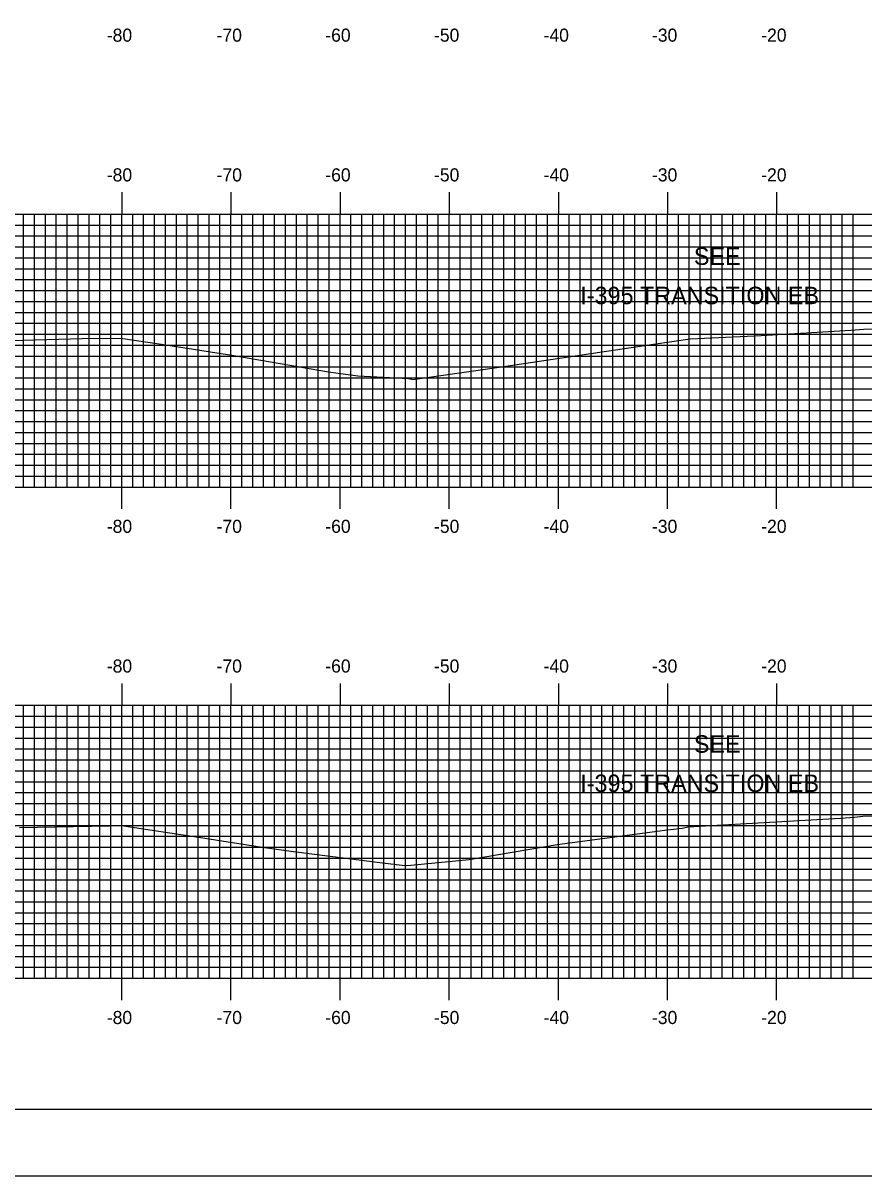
# Model space of a CAD drawing. Extents: x 841782 to 842125, y 363538 to 363758.
# Drawn here: x 841858.3 to 841935.4, y 363537.6 to 363643.2 of the extents above; entities that cross this region are included whole.
import ezdxf

# ---------------------------------------------------------------- set-up
doc = ezdxf.new("R2010")
doc.units = 0
for name, color, linetype in [('ANNOTATION', 7, 'Continuous'), ('BORDER', 7, 'Continuous'), ('H_V ANNOTATION', 7, 'Continuous'), ('M_Roadway_Centerline', 7, 'Continuous'), ('MAJOR', 7, 'Continuous'), ('MINOR', 7, 'Continuous'), ('PLOT BOUNDARY', 7, 'Continuous'), ('S_Roadway_Centerline', 7, 'Continuous')]:
    doc.layers.add(name, color=color, linetype=linetype)

msp = doc.modelspace()

# ---------------------------------------------------------------- linework, layer by layer
at = {"layer": 'BORDER'}
msp.add_lwpolyline([(841797.77, 363543.72), (842117.77, 363543.72), (842117.77, 363753.72), (841797.77, 363753.72)], close=True, dxfattribs=at)
at = {"layer": 'MAJOR'}
for p, q in [((841867.37, 363627.73), (841867.37, 363625.72)), ((841877.37, 363627.73), (841877.37, 363625.72)), ((841887.37, 363627.73), (841887.37, 363625.72)), ((841897.37, 363627.73), (841897.37, 363625.72)), ((841907.37, 363627.73), (841907.37, 363625.72)), ((841917.37, 363627.73), (841917.37, 363625.72)), ((841927.37, 363627.73), (841927.37, 363625.72)), ((841807.37, 363625.72), (842087.37, 363625.72)), ((841807.37, 363625.72), (842087.37, 363625.72)), ((841867.37, 363600.72), (841867.37, 363625.72)), ((841877.37, 363600.72), (841877.37, 363625.72)), ((841887.37, 363600.72), (841887.37, 363625.72)), ((841897.37, 363600.72), (841897.37, 363625.72)), ((841907.37, 363600.72), (841907.37, 363625.72)), ((841917.37, 363600.72), (841917.37, 363625.72)), ((841927.37, 363600.72), (841927.37, 363625.72)), ((841807.37, 363620.72), (842087.37, 363620.72)), ((841807.37, 363615.72), (842087.37, 363615.72)), ((841807.37, 363610.72), (842087.37, 363610.72)), ((841807.37, 363605.72), (842087.37, 363605.72)), ((841807.37, 363600.72), (842087.37, 363600.72)), ((841807.37, 363600.72), (842087.37, 363600.72)), ((841867.37, 363598.72), (841867.37, 363600.72)), ((841877.37, 363598.72), (841877.37, 363600.72)), ((841887.37, 363598.72), (841887.37, 363600.72)), ((841897.37, 363598.72), (841897.37, 363600.72)), ((841907.37, 363598.72), (841907.37, 363600.72)), ((841917.37, 363598.72), (841917.37, 363600.72)), ((841927.37, 363598.72), (841927.37, 363600.72)), ((841867.37, 363582.73), (841867.37, 363580.72)), ((841877.37, 363582.73), (841877.37, 363580.72)), ((841887.37, 363582.73), (841887.37, 363580.72)), ((841897.37, 363582.73), (841897.37, 363580.72)), ((841907.37, 363582.73), (841907.37, 363580.72)), ((841917.37, 363582.73), (841917.37, 363580.72)), ((841927.37, 363582.73), (841927.37, 363580.72)), ((841807.37, 363580.72), (842087.37, 363580.72)), ((841807.37, 363580.72), (842087.37, 363580.72)), ((841867.37, 363555.72), (841867.37, 363580.72)), ((841877.37, 363555.72), (841877.37, 363580.72)), ((841887.37, 363555.72), (841887.37, 363580.72)), ((841897.37, 363555.72), (841897.37, 363580.72)), ((841907.37, 363555.72), (841907.37, 363580.72)), ((841917.37, 363555.72), (841917.37, 363580.72)), ((841927.37, 363555.72), (841927.37, 363580.72)), ((841807.37, 363575.72), (842087.37, 363575.72)), ((841807.37, 363570.72), (842087.37, 363570.72)), ((841807.37, 363565.72), (842087.37, 363565.72)), ((841807.37, 363560.72), (842087.37, 363560.72)), ((841807.37, 363555.72), (842087.37, 363555.72)), ((841807.37, 363555.72), (842087.37, 363555.72)), ((841867.37, 363553.72), (841867.37, 363555.72)), ((841877.37, 363553.72), (841877.37, 363555.72)), ((841887.37, 363553.72), (841887.37, 363555.72)), ((841897.37, 363553.72), (841897.37, 363555.72)), ((841907.37, 363553.72), (841907.37, 363555.72)), ((841917.37, 363553.72), (841917.37, 363555.72)), ((841927.37, 363553.72), (841927.37, 363555.72))]:
    msp.add_line(p, q, dxfattribs=at)
at = {"layer": 'MINOR'}
for p, q in [((841858.37, 363600.72), (841858.37, 363625.72)), ((841859.37, 363600.72), (841859.37, 363625.72)), ((841860.37, 363600.72), (841860.37, 363625.72)), ((841861.37, 363600.72), (841861.37, 363625.72)), ((841862.37, 363600.72), (841862.37, 363625.72)), ((841863.37, 363600.72), (841863.37, 363625.72)), ((841864.37, 363600.72), (841864.37, 363625.72)), ((841865.37, 363600.72), (841865.37, 363625.72)), ((841866.37, 363600.72), (841866.37, 363625.72)), ((841868.37, 363600.72), (841868.37, 363625.72)), ((841869.37, 363600.72), (841869.37, 363625.72)), ((841870.37, 363600.72), (841870.37, 363625.72)), ((841871.37, 363600.72), (841871.37, 363625.72)), ((841872.37, 363600.72), (841872.37, 363625.72)), ((841873.37, 363600.72), (841873.37, 363625.72)), ((841874.37, 363600.72), (841874.37, 363625.72)), ((841875.37, 363600.72), (841875.37, 363625.72)), ((841876.37, 363600.72), (841876.37, 363625.72)), ((841878.37, 363600.72), (841878.37, 363625.72)), ((841879.37, 363600.72), (841879.37, 363625.72)), ((841880.37, 363600.72), (841880.37, 363625.72)), ((841881.37, 363600.72), (841881.37, 363625.72)), ((841882.37, 363600.72), (841882.37, 363625.72)), ((841883.37, 363600.72), (841883.37, 363625.72)), ((841884.37, 363600.72), (841884.37, 363625.72)), ((841885.37, 363600.72), (841885.37, 363625.72)), ((841886.37, 363600.72), (841886.37, 363625.72)), ((841888.37, 363600.72), (841888.37, 363625.72)), ((841889.37, 363600.72), (841889.37, 363625.72)), ((841890.37, 363600.72), (841890.37, 363625.72)), ((841891.37, 363600.72), (841891.37, 363625.72)), ((841892.37, 363600.72), (841892.37, 363625.72)), ((841893.37, 363600.72), (841893.37, 363625.72)), ((841894.37, 363600.72), (841894.37, 363625.72)), ((841895.37, 363600.72), (841895.37, 363625.72)), ((841896.37, 363600.72), (841896.37, 363625.72)), ((841898.37, 363600.72), (841898.37, 363625.72)), ((841899.37, 363600.72), (841899.37, 363625.72)), ((841900.37, 363600.72), (841900.37, 363625.72)), ((841901.37, 363600.72), (841901.37, 363625.72)), ((841902.37, 363600.72), (841902.37, 363625.72)), ((841903.37, 363600.72), (841903.37, 363625.72)), ((841904.37, 363600.72), (841904.37, 363625.72)), ((841905.37, 363600.72), (841905.37, 363625.72)), ((841906.37, 363600.72), (841906.37, 363625.72)), ((841908.37, 363600.72), (841908.37, 363625.72)), ((841909.37, 363600.72), (841909.37, 363625.72)), ((841910.37, 363600.72), (841910.37, 363625.72)), ((841911.37, 363600.72), (841911.37, 363625.72)), ((841912.37, 363600.72), (841912.37, 363625.72)), ((841913.37, 363600.72), (841913.37, 363625.72)), ((841914.37, 363600.72), (841914.37, 363625.72)), ((841915.37, 363600.72), (841915.37, 363625.72)), ((841916.37, 363600.72), (841916.37, 363625.72)), ((841918.37, 363600.72), (841918.37, 363625.72)), ((841919.37, 363600.72), (841919.37, 363625.72)), ((841920.37, 363600.72), (841920.37, 363625.72)), ((841921.37, 363600.72), (841921.37, 363625.72)), ((841922.37, 363600.72), (841922.37, 363625.72)), ((841923.37, 363600.72), (841923.37, 363625.72)), ((841924.37, 363600.72), (841924.37, 363625.72)), ((841925.37, 363600.72), (841925.37, 363625.72)), ((841926.37, 363600.72), (841926.37, 363625.72)), ((841928.37, 363600.72), (841928.37, 363625.72)), ((841929.37, 363600.72), (841929.37, 363625.72)), ((841930.37, 363600.72), (841930.37, 363625.72)), ((841931.37, 363600.72), (841931.37, 363625.72)), ((841932.37, 363600.72), (841932.37, 363625.72)), ((841933.37, 363600.72), (841933.37, 363625.72)), ((841934.37, 363600.72), (841934.37, 363625.72)), ((841807.37, 363624.72), (842087.37, 363624.72)), ((841807.37, 363623.72), (842087.37, 363623.72)), ((841807.37, 363622.72), (842087.37, 363622.72)), ((841807.37, 363621.72), (842087.37, 363621.72)), ((841807.37, 363619.72), (842087.37, 363619.72)), ((841807.37, 363618.72), (842087.37, 363618.72)), ((841807.37, 363617.72), (842087.37, 363617.72)), ((841807.37, 363616.72), (842087.37, 363616.72)), ((841807.37, 363614.72), (842087.37, 363614.72)), ((841807.37, 363613.72), (842087.37, 363613.72)), ((841807.37, 363612.72), (842087.37, 363612.72)), ((841807.37, 363611.72), (842087.37, 363611.72)), ((841807.37, 363609.72), (842087.37, 363609.72)), ((841807.37, 363608.72), (842087.37, 363608.72)), ((841807.37, 363607.72), (842087.37, 363607.72)), ((841807.37, 363606.72), (842087.37, 363606.72)), ((841807.37, 363604.72), (842087.37, 363604.72)), ((841807.37, 363603.72), (842087.37, 363603.72)), ((841807.37, 363602.72), (842087.37, 363602.72)), ((841807.37, 363601.72), (842087.37, 363601.72)), ((841858.37, 363555.72), (841858.37, 363580.72)), ((841859.37, 363555.72), (841859.37, 363580.72)), ((841860.37, 363555.72), (841860.37, 363580.72)), ((841861.37, 363555.72), (841861.37, 363580.72)), ((841862.37, 363555.72), (841862.37, 363580.72)), ((841863.37, 363555.72), (841863.37, 363580.72)), ((841864.37, 363555.72), (841864.37, 363580.72)), ((841865.37, 363555.72), (841865.37, 363580.72)), ((841866.37, 363555.72), (841866.37, 363580.72)), ((841868.37, 363555.72), (841868.37, 363580.72)), ((841869.37, 363555.72), (841869.37, 363580.72)), ((841870.37, 363555.72), (841870.37, 363580.72)), ((841871.37, 363555.72), (841871.37, 363580.72)), ((841872.37, 363555.72), (841872.37, 363580.72)), ((841873.37, 363555.72), (841873.37, 363580.72)), ((841874.37, 363555.72), (841874.37, 363580.72)), ((841875.37, 363555.72), (841875.37, 363580.72)), ((841876.37, 363555.72), (841876.37, 363580.72)), ((841878.37, 363555.72), (841878.37, 363580.72)), ((841879.37, 363555.72), (841879.37, 363580.72)), ((841880.37, 363555.72), (841880.37, 363580.72)), ((841881.37, 363555.72), (841881.37, 363580.72)), ((841882.37, 363555.72), (841882.37, 363580.72)), ((841883.37, 363555.72), (841883.37, 363580.72)), ((841884.37, 363555.72), (841884.37, 363580.72)), ((841885.37, 363555.72), (841885.37, 363580.72)), ((841886.37, 363555.72), (841886.37, 363580.72)), ((841888.37, 363555.72), (841888.37, 363580.72)), ((841889.37, 363555.72), (841889.37, 363580.72)), ((841890.37, 363555.72), (841890.37, 363580.72)), ((841891.37, 363555.72), (841891.37, 363580.72)), ((841892.37, 363555.72), (841892.37, 363580.72)), ((841893.37, 363555.72), (841893.37, 363580.72)), ((841894.37, 363555.72), (841894.37, 363580.72)), ((841895.37, 363555.72), (841895.37, 363580.72)), ((841896.37, 363555.72), (841896.37, 363580.72)), ((841898.37, 363555.72), (841898.37, 363580.72)), ((841899.37, 363555.72), (841899.37, 363580.72)), ((841900.37, 363555.72), (841900.37, 363580.72)), ((841901.37, 363555.72), (841901.37, 363580.72)), ((841902.37, 363555.72), (841902.37, 363580.72)), ((841903.37, 363555.72), (841903.37, 363580.72)), ((841904.37, 363555.72), (841904.37, 363580.72)), ((841905.37, 363555.72), (841905.37, 363580.72)), ((841906.37, 363555.72), (841906.37, 363580.72)), ((841908.37, 363555.72), (841908.37, 363580.72)), ((841909.37, 363555.72), (841909.37, 363580.72)), ((841910.37, 363555.72), (841910.37, 363580.72)), ((841911.37, 363555.72), (841911.37, 363580.72)), ((841912.37, 363555.72), (841912.37, 363580.72)), ((841913.37, 363555.72), (841913.37, 363580.72)), ((841914.37, 363555.72), (841914.37, 363580.72)), ((841915.37, 363555.72), (841915.37, 363580.72)), ((841916.37, 363555.72), (841916.37, 363580.72)), ((841918.37, 363555.72), (841918.37, 363580.72)), ((841919.37, 363555.72), (841919.37, 363580.72)), ((841920.37, 363555.72), (841920.37, 363580.72)), ((841921.37, 363555.72), (841921.37, 363580.72)), ((841922.37, 363555.72), (841922.37, 363580.72)), ((841923.37, 363555.72), (841923.37, 363580.72)), ((841924.37, 363555.72), (841924.37, 363580.72)), ((841925.37, 363555.72), (841925.37, 363580.72)), ((841926.37, 363555.72), (841926.37, 363580.72)), ((841928.37, 363555.72), (841928.37, 363580.72)), ((841929.37, 363555.72), (841929.37, 363580.72)), ((841930.37, 363555.72), (841930.37, 363580.72)), ((841931.37, 363555.72), (841931.37, 363580.72)), ((841932.37, 363555.72), (841932.37, 363580.72)), ((841933.37, 363555.72), (841933.37, 363580.72)), ((841934.37, 363555.72), (841934.37, 363580.72)), ((841807.37, 363579.72), (842087.37, 363579.72)), ((841807.37, 363578.72), (842087.37, 363578.72)), ((841807.37, 363577.72), (842087.37, 363577.72)), ((841807.37, 363576.72), (842087.37, 363576.72)), ((841807.37, 363574.72), (842087.37, 363574.72)), ((841807.37, 363573.72), (842087.37, 363573.72)), ((841807.37, 363572.72), (842087.37, 363572.72)), ((841807.37, 363571.72), (842087.37, 363571.72)), ((841807.37, 363569.72), (842087.37, 363569.72)), ((841807.37, 363568.72), (842087.37, 363568.72)), ((841807.37, 363567.72), (842087.37, 363567.72)), ((841807.37, 363566.72), (842087.37, 363566.72)), ((841807.37, 363564.72), (842087.37, 363564.72)), ((841807.37, 363563.72), (842087.37, 363563.72)), ((841807.37, 363562.72), (842087.37, 363562.72)), ((841807.37, 363561.72), (842087.37, 363561.72)), ((841807.37, 363559.72), (842087.37, 363559.72)), ((841807.37, 363558.72), (842087.37, 363558.72)), ((841807.37, 363557.72), (842087.37, 363557.72)), ((841807.37, 363556.72), (842087.37, 363556.72))]:
    msp.add_line(p, q, dxfattribs=at)
at = {"layer": 'PLOT BOUNDARY'}
msp.add_lwpolyline([(841781.59, 363537.6), (842121.59, 363537.6), (842121.59, 363757.6), (841781.59, 363757.6)], close=True, dxfattribs=at)
at = {"layer": 'S_Roadway_Centerline'}
for points in [[(841854.04, 363614.05), (841863.74, 363614.32), (841865.93, 363614.37), (841867.48, 363614.34), (841871.02, 363613.82), (841877.44, 363612.79), (841886.32, 363611.27), (841888.99, 363610.92), (841893.63, 363610.66), (841894.04, 363610.58), (841899.37, 363611.34), (841901.94, 363611.69), (841916.1, 363613.81), (841919.46, 363614.3), (841921.42, 363614.39), (841925.95, 363614.6), (841934.18, 363615.09), (841935.36, 363615.19), (841938.12, 363615.23)], [(841858.01, 363569.53), (841866.24, 363569.69), (841867.32, 363569.73), (841867.52, 363569.68), (841874.39, 363568.64), (841880.22, 363567.73), (841883.09, 363567.32), (841891.02, 363566.32), (841893.31, 363566.03), (841893.42, 363566.03), (841893.85, 363566.09), (841899.21, 363566.6), (841907.27, 363567.96), (841917.13, 363569.29), (841918.73, 363569.48), (841919.22, 363569.59), (841929.97, 363570.19), (841933.21, 363570.38), (841934.52, 363570.46), (841935.26, 363570.58), (841938.03, 363570.66)]]:
    msp.add_lwpolyline(points, dxfattribs=at)

# ---------------------------------------------------------------- texts
at = {"layer": 'ANNOTATION'}
for s, p in [('SEE', (841919.79, 363621.07)), ('I-395 TRANSITION EB', (841909.38, 363617.47)), ('SEE', (841919.79, 363576.38)), ('I-395 TRANSITION EB', (841909.38, 363572.78))]:
    msp.add_text(s, height=1.6, dxfattribs=at).set_placement(p)
at = {"layer": 'H_V ANNOTATION'}
for s, p in [('-80', (841866, 363641.52)), ('-70', (841876.06, 363641.52)), ('-60', (841886.02, 363641.52)), ('-50', (841895.98, 363641.52)), ('-40', (841906.02, 363641.52)), ('-30', (841915.95, 363641.52)), ('-20', (841925.96, 363641.52)), ('-80', (841866, 363628.72)), ('-70', (841876.06, 363628.72)), ('-60', (841886.02, 363628.72)), ('-50', (841895.98, 363628.72)), ('-40', (841906.02, 363628.72)), ('-30', (841915.95, 363628.72)), ('-20', (841925.96, 363628.72)), ('-80', (841866, 363596.52)), ('-70', (841876.06, 363596.52)), ('-60', (841886.02, 363596.52)), ('-50', (841895.98, 363596.52)), ('-40', (841906.02, 363596.52)), ('-30', (841915.95, 363596.52)), ('-20', (841925.96, 363596.52)), ('-80', (841866, 363583.72)), ('-70', (841876.06, 363583.72)), ('-60', (841886.02, 363583.72)), ('-50', (841895.98, 363583.72)), ('-40', (841906.02, 363583.72)), ('-30', (841915.95, 363583.72)), ('-20', (841925.96, 363583.72)), ('-80', (841866, 363551.52)), ('-70', (841876.06, 363551.52)), ('-60', (841886.02, 363551.52)), ('-50', (841895.98, 363551.52)), ('-40', (841906.02, 363551.52)), ('-30', (841915.95, 363551.52)), ('-20', (841925.96, 363551.52))]:
    msp.add_text(s, height=1.2, dxfattribs=at).set_placement(p)
at = {"layer": 'M_Roadway_Centerline'}
for s, p in [('C', (841935.35, 363615.19)), ('L', (841935.36, 363615.19)), ('C', (841935.26, 363570.58)), ('L', (841935.26, 363570.57))]:
    msp.add_text(s, height=0.0146, dxfattribs=at).set_placement(p)

doc.saveas('drawing.dxf')
